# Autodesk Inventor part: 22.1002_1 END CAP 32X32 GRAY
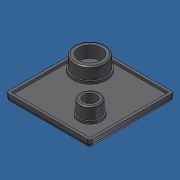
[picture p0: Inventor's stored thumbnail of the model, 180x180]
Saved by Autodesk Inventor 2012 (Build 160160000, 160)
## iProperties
Created: 2007-01
Part Number: 22.1002_1 END CAP 32X32 GRAY
Document SubType Name: Modeling
Designer: Andy Moles
Material: ABS Plastic
Density: 1.06 g/cm^3
Mass: 2.70879 g
Surface Area: 31.6409 cm^2
Volume: 2.55546 cm^3
Author: Andy Moles
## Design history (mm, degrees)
sketch "Sketch1"
  geometry: L1 (-22.5, 22.5)-(9.5, 22.5); L2 (9.5, 22.5)-(9.5, -9.5); L3 (9.5, -9.5)-(-22.5, -9.5); L4 (-22.5, -9.5)-(-22.5, 22.5); 1 further point
  constraints: 8 end point, 2 parallel, 1 horizontal, 1 perpendicular
  dimensions: "WIDTH1" = 32 distance of L1.end L2.end; "WIDTH2" = 32 distance of L1.start L1.end; "d2" = 22.5 distance from line of point (0, 0) L1; "d3" = 9.5 distance from line of point (0, 0) L2
extrude "Extrusion1" new body sketch "Sketch1" distance "d4" = 3; taper "d5" = 0 deg
fillet "Fillet1" dims "d6" = 1
fillet "Fillet2" dims "d7" = 1.5
sketch "Sketch2"
  geometry: L1 (8.5, -9.5)-(-21.5, -9.5) reference; L2 (9.5, 21.5)-(9.5, -8.5) reference; L3 (-21.5, 22.5)-(8.5, 22.5) reference; L4 (-22.5, -8.5)-(-22.5, 21.5) reference; C1 r 2.375 at (0, 0); C2 r 3.825 at (0, 0); C3 r 5.875 at (-14.65, 14.65); C4 r 4.25 at (-14.65, 14.65)
  constraints: 4 centre point, 2 coincident
  dimensions: "d8" = 4.75 diameter of C1; "d9" = 7.65 diameter of C2; "d10" = 9.5 distance from line of C1.centre L2; "d11" = 9.5 distance from line of C1.centre L1; "d12" = 8.5 diameter of C4; "d13" = 11.75 diameter of C3; "d14" = 7.85 distance from line of C3.centre L4; "d15" = 7.85 distance from line of C4.centre L3
extrude "Extrusion2" join sketch "Sketch2" distance "d16" = 4.5; taper "d17" = 0 deg
fillet "Fillet3" dims "d18" = 0.5
sketch "Sketch3"
  geometry: C1 r 2.375 at (0, 0) reference; C2 r 2.375 at (0, 0) reference; C3 r 2.5 at (0, 0); 1 further point
  constraints: 1 centre point, 1 coincident
  dimensions: "d21" = 5 diameter of C3
extrude "Extrusion3" cut sketch "Sketch3" distance "d19" = 10; taper "d20" = 0 deg
shell "Shell1" dims "d22" = 1
sketch "Sketch4"
  geometry: L1 (-0.5, -29.5)-(-0.5, 0.5) reference; L2 (-0.5, 0.5)-(29.5, 0.5) reference; L3 (29.5, 0.5)-(29.5, -29.5) reference; L4 (29.5, -29.5)-(-0.5, -29.5) reference; C1 r 3.5 at (21, -21) reference
extrude "Extrusion4" join sketch "Sketch4" distance "d23" = 1; taper "d24" = 0 deg
sketch "Sketch5"
  geometry: C1 r 3.825 at (0, 0) reference; C2 r 5.875 at (-14.65, 14.65) reference; C3 r 4.325 at (0, 0); C4 r 6.375 at (-14.65, 14.65); C5 r 5.875 at (-14.65, 14.65) reference; 1 further point
  constraints: 2 centre point
  dimensions: "d25" = 0.5 radial gap between concentric circles of C3 C1; "d26" = 0.5 radial gap between concentric circles of C4 C5 (= d25)
extrude "Extrusion5" join sketch "Sketch5" distance "d27" = 1; taper "d28" = 0 deg
body "Solid1"
node "Projected Loop1"
